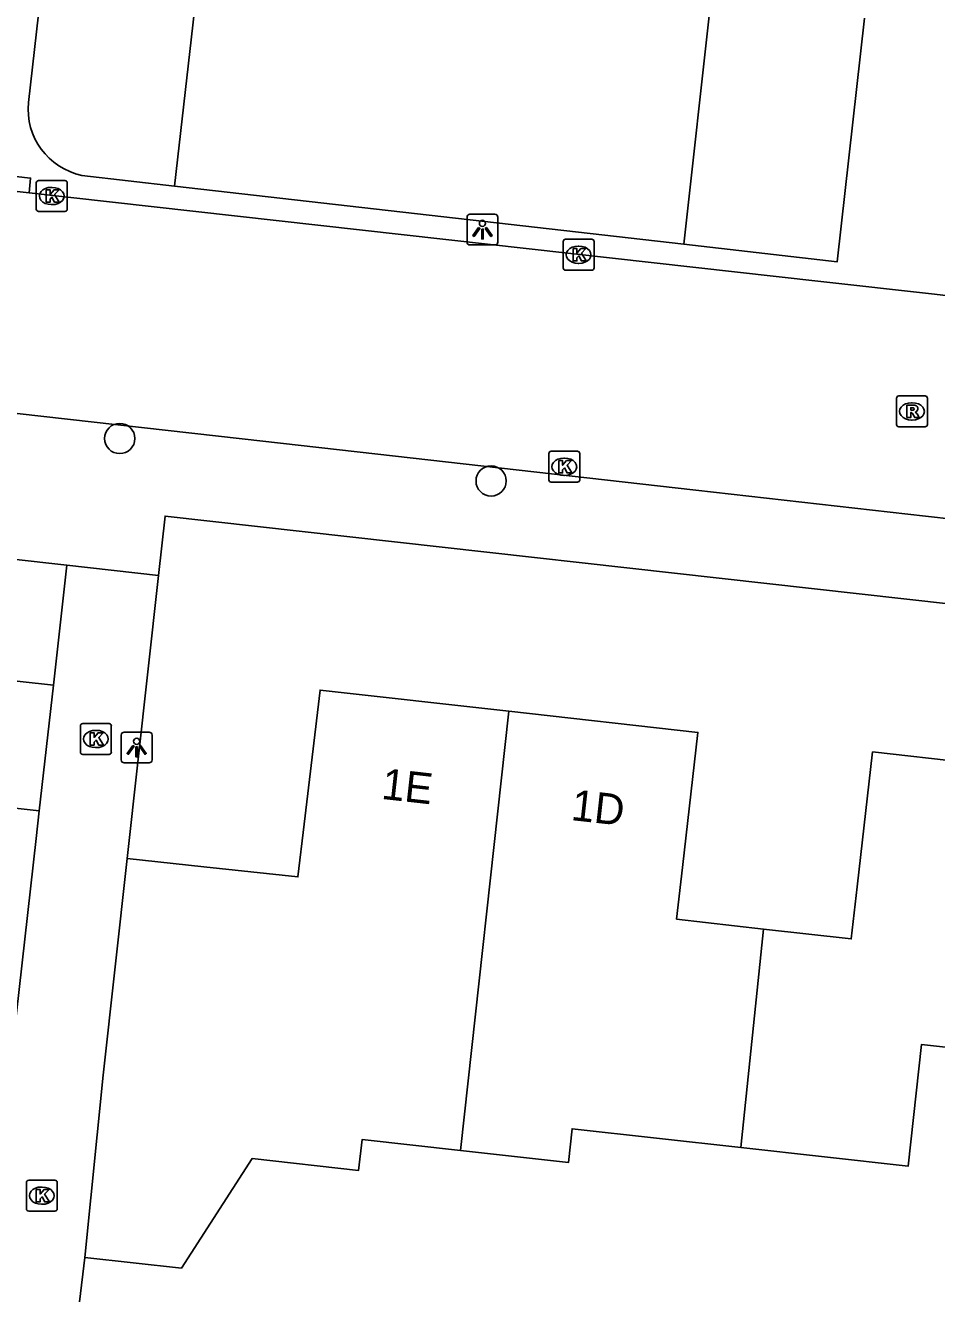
# Model space of a CAD drawing. Extents: x 162082 to 163393, y 388091 to 388632.
# Drawn here: x 162880.67 to 162910.17, y 388302.07 to 388343.14 of the extents above; entities that cross this region are included whole.
import ezdxf

# ---------------------------------------------------------------- set-up
doc = ezdxf.new("R2010")
doc.units = 0
for name, color, linetype in [('IMGEO_Boom', 7, 'Continuous'), ('IMGEO_Groenvoorziening', 7, 'Continuous'), ('IMGEO_Kolk', 7, 'Continuous'), ('IMGEO_Lichtpunt', 7, 'Continuous'), ('IMGEO_Muur', 7, 'Continuous'), ('IMGEO_Pand', 7, 'Continuous'), ('IMGEO_Pand_nummerreeks', 7, 'Continuous'), ('IMGEO_Rijbaan_lokaal_open', 7, 'Continuous'), ('IMGEO_Rioolput', 7, 'Continuous'), ('IMGEO_Voetpad_open', 7, 'Continuous')]:
    doc.layers.add(name, color=color, linetype=linetype)

msp = doc.modelspace()

# ---------------------------------------------------------------- linework, layer by layer
at = {"layer": 'IMGEO_Boom'}
for centre in [(162883.725, 388329.762), (162895.748, 388328.386)]:
    msp.add_circle(centre, 0.489, dxfattribs=at)
at = {"layer": 'IMGEO_Groenvoorziening'}
for points in [[(162885.495, 388337.937), (162886.389, 388345.809)], [(162902.866, 388343.939), (162901.986, 388336.052)]]:
    msp.add_lwpolyline(points, dxfattribs=at)
at = {"layer": 'IMGEO_Kolk'}
for p, q in [((162881.023, 388337.188), (162881.023, 388338.04)), ((162881.098, 388338.114), (162881.95, 388338.114)), ((162881.511, 388337.894), (162881.536, 388337.894)), ((162882.024, 388338.04), (162882.024, 388337.188)), ((162881.95, 388337.114), (162881.098, 388337.114)), ((162881.534, 388337.334), (162881.509, 388337.334)), ((162898.08, 388335.285), (162898.08, 388336.137)), ((162898.155, 388336.211), (162899.007, 388336.211)), ((162898.568, 388335.991), (162898.593, 388335.991)), ((162899.081, 388336.137), (162899.081, 388335.285)), ((162898.591, 388335.431), (162898.566, 388335.431)), ((162899.007, 388335.211), (162898.155, 388335.211)), ((162897.616, 388328.421), (162897.616, 388329.273)), ((162897.691, 388329.347), (162898.543, 388329.347)), ((162898.617, 388329.273), (162898.617, 388328.421)), ((162898.104, 388329.127), (162898.129, 388329.127)), ((162898.127, 388328.567), (162898.102, 388328.567)), ((162898.543, 388328.347), (162897.691, 388328.347)), ((162882.451, 388319.605), (162882.451, 388320.457)), ((162882.526, 388320.531), (162883.378, 388320.531)), ((162882.939, 388320.311), (162882.964, 388320.311)), ((162883.452, 388320.457), (162883.452, 388319.605)), ((162883.378, 388319.531), (162882.526, 388319.531)), ((162882.962, 388319.751), (162882.937, 388319.751)), ((162880.701, 388304.817), (162880.701, 388305.669)), ((162880.776, 388305.743), (162881.628, 388305.743)), ((162881.189, 388305.523), (162881.214, 388305.523)), ((162881.702, 388305.669), (162881.702, 388304.817)), ((162881.628, 388304.743), (162880.776, 388304.743)), ((162881.212, 388304.963), (162881.187, 388304.963))]:
    msp.add_line(p, q, dxfattribs=at)
for points in [[(162881.023, 388337.188), (162881.023, 388338.04)], [(162881.098, 388338.114), (162881.95, 388338.114)], [(162882.024, 388338.04), (162882.024, 388337.188)], [(162881.344, 388337.814), (162881.467, 388337.814), (162881.467, 388337.663), (162881.597, 388337.814), (162881.761, 388337.814), (162881.615, 388337.663), (162881.768, 388337.414), (162881.616, 388337.414), (162881.531, 388337.578), (162881.467, 388337.511), (162881.467, 388337.414), (162881.344, 388337.414), (162881.344, 388337.814)], [(162881.95, 388337.114), (162881.098, 388337.114)], [(162898.08, 388335.285), (162898.08, 388336.137)], [(162898.155, 388336.211), (162899.007, 388336.211)], [(162898.401, 388335.911), (162898.524, 388335.911), (162898.524, 388335.76), (162898.654, 388335.911), (162898.818, 388335.911), (162898.672, 388335.76), (162898.825, 388335.511), (162898.673, 388335.511), (162898.588, 388335.675), (162898.524, 388335.608), (162898.524, 388335.511), (162898.401, 388335.511), (162898.401, 388335.911)], [(162899.081, 388336.137), (162899.081, 388335.285)], [(162899.007, 388335.211), (162898.155, 388335.211)], [(162897.616, 388328.421), (162897.616, 388329.273)], [(162897.691, 388329.347), (162898.543, 388329.347)], [(162898.617, 388329.273), (162898.617, 388328.421)], [(162897.937, 388329.047), (162898.06, 388329.047), (162898.06, 388328.896), (162898.19, 388329.047), (162898.354, 388329.047), (162898.208, 388328.896), (162898.361, 388328.647), (162898.209, 388328.647), (162898.124, 388328.811), (162898.06, 388328.744), (162898.06, 388328.647), (162897.937, 388328.647), (162897.937, 388329.047)], [(162898.543, 388328.347), (162897.691, 388328.347)], [(162882.451, 388319.605), (162882.451, 388320.457)], [(162882.526, 388320.531), (162883.378, 388320.531)], [(162882.772, 388320.231), (162882.895, 388320.231), (162882.895, 388320.08), (162883.025, 388320.231), (162883.189, 388320.231), (162883.043, 388320.08), (162883.196, 388319.831), (162883.044, 388319.831), (162882.959, 388319.995), (162882.895, 388319.928), (162882.895, 388319.831), (162882.772, 388319.831), (162882.772, 388320.231)], [(162883.452, 388320.457), (162883.452, 388319.605)], [(162883.378, 388319.531), (162882.526, 388319.531)], [(162880.701, 388304.817), (162880.701, 388305.669)], [(162880.776, 388305.743), (162881.628, 388305.743)], [(162881.022, 388305.443), (162881.145, 388305.443), (162881.145, 388305.292), (162881.275, 388305.443), (162881.439, 388305.443), (162881.293, 388305.292), (162881.446, 388305.043), (162881.294, 388305.043), (162881.209, 388305.207), (162881.145, 388305.14), (162881.145, 388305.043), (162881.022, 388305.043), (162881.022, 388305.443)], [(162881.702, 388305.669), (162881.702, 388304.817)], [(162881.628, 388304.743), (162880.776, 388304.743)]]:
    msp.add_lwpolyline(points, dxfattribs=at)
for centre, start, end in [((162881.1, 388338.038), 91.552, 178.448), ((162881.1, 388338.038), 91.552, 178.448), ((162881.948, 388338.038), 1.552, 88.448), ((162881.948, 388338.038), 1.552, 88.448), ((162881.1, 388337.19), 181.552, 268.448), ((162881.1, 388337.19), 181.552, 268.448), ((162881.948, 388337.19), 271.552, 358.448), ((162881.948, 388337.19), 271.552, 358.448), ((162898.157, 388336.135), 91.552, 178.448), ((162898.157, 388336.135), 91.552, 178.448), ((162899.005, 388336.135), 1.552, 88.448), ((162899.005, 388336.135), 1.552, 88.448), ((162898.157, 388335.287), 181.552, 268.448), ((162898.157, 388335.287), 181.552, 268.448), ((162899.005, 388335.287), 271.552, 358.448), ((162899.005, 388335.287), 271.552, 358.448), ((162897.693, 388329.271), 91.552, 178.448), ((162897.693, 388329.271), 91.552, 178.448), ((162898.541, 388329.271), 1.552, 88.448), ((162898.541, 388329.271), 1.552, 88.448), ((162897.693, 388328.423), 181.552, 268.448), ((162897.693, 388328.423), 181.552, 268.448), ((162898.541, 388328.423), 271.552, 358.448), ((162898.541, 388328.423), 271.552, 358.448), ((162882.528, 388320.455), 91.552, 178.448), ((162882.528, 388320.455), 91.552, 178.448), ((162883.376, 388320.455), 1.552, 88.448), ((162883.376, 388320.455), 1.552, 88.448), ((162882.528, 388319.607), 181.552, 268.448), ((162882.528, 388319.607), 181.552, 268.448), ((162883.376, 388319.607), 271.552, 358.448), ((162883.376, 388319.607), 271.552, 358.448), ((162880.778, 388305.667), 91.552, 178.448), ((162880.778, 388305.667), 91.552, 178.448), ((162881.626, 388305.667), 1.552, 88.448), ((162881.626, 388305.667), 1.552, 88.448), ((162880.778, 388304.819), 181.552, 268.448), ((162880.778, 388304.819), 181.552, 268.448), ((162881.626, 388304.819), 271.552, 358.448), ((162881.626, 388304.819), 271.552, 358.448)]:
    msp.add_arc(centre, 0.0765, start, end, dxfattribs=at)
for centre, major_axis, ratio, start_param, end_param in [((162881.51, 388337.614), (-0.387, 0.002), 0.722429, 4.712389, 7.853982), ((162881.535, 388337.614), (-0.39, 0.002), 0.717154, 1.570796, 4.712389), ((162898.567, 388335.711), (-0.387, 0.002), 0.722429, 4.712389, 7.853982), ((162898.592, 388335.711), (-0.39, 0.002), 0.717154, 1.570796, 4.712389), ((162898.103, 388328.847), (-0.387, 0.002), 0.722429, 4.712389, 7.853982), ((162898.128, 388328.847), (-0.39, 0.002), 0.717154, 1.570796, 4.712389), ((162882.938, 388320.031), (-0.387, 0.002), 0.722429, 4.712389, 7.853982), ((162882.963, 388320.031), (-0.39, 0.002), 0.717154, 1.570796, 4.712389), ((162881.188, 388305.243), (-0.387, 0.002), 0.722429, 4.712389, 7.853982), ((162881.213, 388305.243), (-0.39, 0.002), 0.717154, 1.570796, 4.712389)]:
    msp.add_ellipse(centre, major_axis=major_axis, ratio=ratio, start_param=start_param, end_param=end_param, dxfattribs=at)
at = {"layer": 'IMGEO_Lichtpunt'}
for p, q in [((162894.97, 388336.929), (162894.97, 388336.122)), ((162894.97, 388336.929), (162894.97, 388336.122)), ((162895.872, 388337.024), (162895.064, 388337.024)), ((162895.872, 388337.024), (162895.064, 388337.024)), ((162895.966, 388336.122), (162895.966, 388336.929)), ((162895.966, 388336.122), (162895.966, 388336.929)), ((162895.064, 388336.028), (162895.872, 388336.028)), ((162895.064, 388336.028), (162895.872, 388336.028)), ((162884.676, 388320.254), (162883.868, 388320.254)), ((162884.676, 388320.254), (162883.868, 388320.254)), ((162883.774, 388320.159), (162883.774, 388319.352)), ((162883.774, 388320.159), (162883.774, 388319.352)), ((162884.77, 388319.352), (162884.77, 388320.159)), ((162884.77, 388319.352), (162884.77, 388320.159)), ((162883.868, 388319.258), (162884.676, 388319.258)), ((162883.868, 388319.258), (162884.676, 388319.258))]:
    msp.add_line(p, q, dxfattribs=at)
for points in [[(162895.344, 388336.593), (162895.383, 388336.565), (162895.195, 388336.303), (162895.157, 388336.33), (162895.344, 388336.593)], [(162895.446, 388336.545), (162895.493, 388336.545), (162895.493, 388336.223), (162895.446, 388336.223), (162895.446, 388336.545)], [(162895.556, 388336.565), (162895.594, 388336.592), (162895.781, 388336.33), (162895.742, 388336.302), (162895.556, 388336.565)], [(162884.148, 388319.823), (162884.187, 388319.795), (162883.999, 388319.533), (162883.961, 388319.56), (162884.148, 388319.823)], [(162884.36, 388319.795), (162884.398, 388319.822), (162884.585, 388319.56), (162884.546, 388319.532), (162884.36, 388319.795)], [(162884.25, 388319.775), (162884.297, 388319.775), (162884.297, 388319.453), (162884.25, 388319.453), (162884.25, 388319.775)]]:
    msp.add_lwpolyline(points, dxfattribs=at)
for centre in [(162895.469, 388336.727), (162884.273, 388319.957)]:
    msp.add_circle(centre, 0.0994, dxfattribs=at)
for centre, start, end in [((162895.064, 388336.929), 90, 180), ((162895.064, 388336.929), 90, 180), ((162895.872, 388336.929), 0, 90), ((162895.872, 388336.929), 0, 90), ((162895.064, 388336.122), 180, 270), ((162895.064, 388336.122), 180, 270), ((162895.872, 388336.122), 270, 0), ((162895.872, 388336.122), 270, 360), ((162883.868, 388320.159), 90, 180), ((162883.868, 388320.159), 90, 180), ((162884.676, 388320.159), 0, 90), ((162884.676, 388320.159), 0, 90), ((162883.868, 388319.352), 180, 270), ((162883.868, 388319.352), 180, 270), ((162884.676, 388319.352), 270, 0), ((162884.676, 388319.352), 270, 360)]:
    msp.add_arc(centre, 0.0946, start, end, dxfattribs=at)
at = {"layer": 'IMGEO_Muur'}
msp.add_lwpolyline([(162881.014, 388316.806), (162879.636, 388304.63)], dxfattribs=at)
at = {"layer": 'IMGEO_Pand'}
for points in [[(162873.336, 388323.497), (162879.499, 388322.807), (162879.41, 388322.012), (162881.575, 388321.77)], [(162881.575, 388321.77), (162881.114, 388317.7)], [(162883.969, 388316.16), (162886.447, 388315.894), (162889.495, 388315.567), (162889.697, 388317.27), (162890.211, 388321.615), (162896.323, 388320.93)], [(162896.323, 388320.93), (162894.755, 388306.71)], [(162896.323, 388320.93), (162902.442, 388320.245), (162901.945, 388315.874), (162901.754, 388314.199), (162904.571, 388313.878)], [(162904.571, 388313.878), (162907.407, 388313.555), (162907.599, 388315.242), (162908.096, 388319.615), (162914.202, 388318.92)], [(162881.114, 388317.7), (162876.019, 388318.271), (162875.392, 388312.668), (162869.223, 388313.359)], [(162882.593, 388303.237), (162883.192, 388309.144), (162883.969, 388316.16)], [(162903.836, 388306.803), (162904.571, 388313.878)], [(162913.18, 388309.749), (162909.677, 388310.134), (162909.255, 388306.202), (162903.836, 388306.803)], [(162903.836, 388306.803), (162898.368, 388307.41), (162898.257, 388306.321), (162894.755, 388306.71)], [(162894.755, 388306.71), (162891.576, 388307.063), (162891.46, 388306.061), (162888.007, 388306.445), (162885.723, 388302.89), (162882.593, 388303.237)]]:
    msp.add_lwpolyline(points, dxfattribs=at)
at = {"layer": 'IMGEO_Rijbaan_lokaal_open'}
for points in [[(162871.19, 388338.785), (162880.788, 388337.712)], [(162880.788, 388337.712), (162906.331, 388334.857), (162910.107, 388334.435), (162937.647, 388331.155)], [(162937.375, 388324.139), (162927.727, 388325.228), (162920.38, 388326.057), (162909.812, 388327.25), (162902.379, 388328.088), (162891.415, 388329.326), (162887.687, 388329.747), (162880.401, 388330.569)]]:
    msp.add_lwpolyline(points, dxfattribs=at)
at = {"layer": 'IMGEO_Rioolput'}
for p, q in [((162908.872, 388330.213), (162908.872, 388331.065)), ((162908.947, 388331.139), (162909.799, 388331.139)), ((162909.36, 388330.919), (162909.385, 388330.919)), ((162909.873, 388331.065), (162909.873, 388330.213)), ((162909.799, 388330.139), (162908.947, 388330.139)), ((162909.383, 388330.359), (162909.358, 388330.359))]:
    msp.add_line(p, q, dxfattribs=at)
for points in [[(162908.872, 388330.213), (162908.872, 388331.065)], [(162908.947, 388331.139), (162909.799, 388331.139)], [(162909.873, 388331.065), (162909.873, 388330.213)], [(162909.461, 388330.837), (162909.209, 388330.839), (162909.209, 388330.439)], [(162909.209, 388330.439), (162909.333, 388330.439), (162909.333, 388330.601), (162909.344, 388330.601)], [(162909.387, 388330.758), (162909.333, 388330.758), (162909.333, 388330.677)], [(162909.333, 388330.677), (162909.385, 388330.677)], [(162909.391, 388330.572), (162909.462, 388330.439), (162909.602, 388330.439), (162909.537, 388330.565)], [(162909.799, 388330.139), (162908.947, 388330.139)]]:
    msp.add_lwpolyline(points, dxfattribs=at)
for centre, radius, start, end in [((162908.949, 388331.063), 0.0765, 91.552, 178.448), ((162908.949, 388331.063), 0.0765, 91.552, 178.448), ((162909.797, 388331.063), 0.0765, 1.552, 88.448), ((162909.797, 388331.063), 0.0765, 1.552, 88.448), ((162909.343, 388330.548), 0.0533, 26.0293, 88.6989), ((162909.369, 388330.866), 0.19, 274.7715, 282.9687), ((162909.393, 388330.662), 0.0964, 77.0061, 93.1865), ((162909.407, 388330.719), 0.0378, 276.6634, 79.6772), ((162909.46, 388330.727), 0.109, 350.3612, 89.416), ((162909.458, 388330.727), 0.112, 277.5842, 350.9817), ((162909.442, 388330.512), 0.108, 29.5134, 73.7905), ((162908.949, 388330.215), 0.0765, 181.552, 268.448), ((162908.949, 388330.215), 0.0765, 181.552, 268.448), ((162909.797, 388330.215), 0.0765, 271.552, 358.448), ((162909.797, 388330.215), 0.0765, 271.552, 358.448)]:
    msp.add_arc(centre, radius, start, end, dxfattribs=at)
for centre, major_axis, ratio, start_param, end_param in [((162909.359, 388330.639), (-0.387, 0.002), 0.722429, 4.712389, 7.853982), ((162909.384, 388330.639), (-0.39, 0.002), 0.717154, 1.570796, 4.712389)]:
    msp.add_ellipse(centre, major_axis=major_axis, ratio=ratio, start_param=start_param, end_param=end_param, dxfattribs=at)
at = {"layer": 'IMGEO_Voetpad_open'}
for points in [[(162880.77, 388340.639), (162881.421, 388346.373)], [(162907.834, 388343.376), (162906.954, 388335.484), (162901.986, 388336.052)], [(162880.788, 388337.712), (162880.84, 388338.193), (162871.635, 388339.233)], [(162885.495, 388337.937), (162882.497, 388338.28)], [(162901.986, 388336.052), (162885.495, 388337.937)], [(162882.015, 388325.663), (162868.576, 388327.156), (162796.49, 388335.147)], [(162936.982, 388321.452), (162936.117, 388321.549), (162885.195, 388327.249), (162884.982, 388325.32)], [(162882.015, 388325.663), (162881.575, 388321.77)], [(162884.982, 388325.32), (162882.015, 388325.663)], [(162883.969, 388316.16), (162884.982, 388325.32)], [(162881.114, 388317.7), (162881.014, 388316.806), (162879.636, 388304.63), (162879.611, 388304.409)], [(162907.36, 388264.58), (162908.073, 388271.01), (162910.054, 388288.891), (162907.123, 388289.226), (162886.23, 388291.615), (162886.758, 388296.567), (162881.865, 388297.138), (162882.593, 388303.237)]]:
    msp.add_lwpolyline(points, dxfattribs=at)
msp.add_arc((162882.955, 388340.427), 2.196, 174.4672, 257.9477, dxfattribs=at)

# ---------------------------------------------------------------- texts
at = {"layer": 'IMGEO_Pand_nummerreeks'}
for s, p in [('1E', (162892.171, 388318.095)), ('1D', (162898.309, 388317.408))]:
    msp.add_text(s, height=1, rotation=353.6089, dxfattribs=at).set_placement(p)

doc.saveas('drawing.dxf')
